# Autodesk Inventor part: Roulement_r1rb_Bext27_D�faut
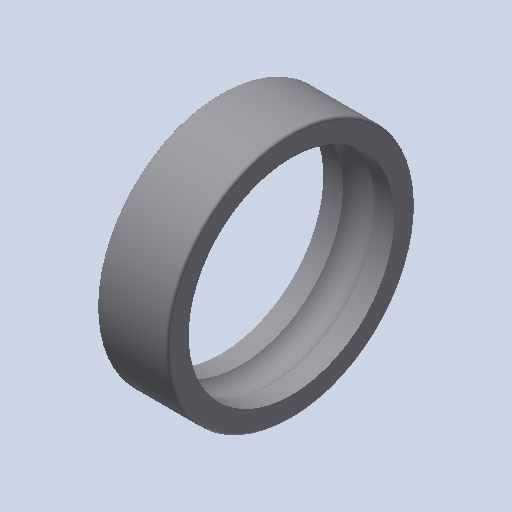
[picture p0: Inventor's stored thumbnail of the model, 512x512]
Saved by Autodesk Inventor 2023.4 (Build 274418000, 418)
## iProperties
Created: 2011-01
Part Number: Roulement_r1rb_Bext27_D�faut
Document SubType Name: Modeling
Designer: eric
Density: 1 g/cm^3
Mass: 1.39224 g
Surface Area: 16.9695 cm^2
Volume: 1.39224 cm^3
Material: Générique
Appearance: Par défaut
Author: eric
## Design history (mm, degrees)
feature "Base1"
node "Corps solides"
node "Corps surfaciques"
node "Solide1"
